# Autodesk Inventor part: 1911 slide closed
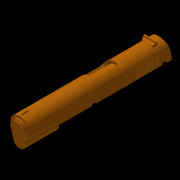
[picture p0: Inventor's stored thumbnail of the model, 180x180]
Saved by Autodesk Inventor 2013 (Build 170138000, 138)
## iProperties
Created: 2012-12
Part Number: 1911 slide closed
Material: Generic
Document SubType Name: Modeling
Designer: John
Density: 1 g/cm^3
Author: John
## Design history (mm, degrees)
sketch "Sketch1"
  geometry: L1 (-11.633, -12.598)-(-11.633, 4.424); L2 (11.633, -12.598)-(11.633, 4.424); L3 (-8.128, -16.129)-(-8.128, -12.598); L4 (8.128, -16.129)-(8.128, -12.598); L5 (-11.633, -12.598)-(-8.128, -12.598); L6 (8.128, -12.598)-(11.633, -12.598); C1 r 8.877 at (0, 0); C2 r 6.35 at (0, -16.129); A1 r 12.446 centre (0, 0) between (11.633, 4.424) and (-11.633, 4.424); A2 r 8.128 centre (0, -16.129) between (-8.128, -16.129) and (8.128, -16.129); 1 further point
  constraints: 12 end point, 4 centre point, 4 perpendicular, 4 point on circle, 3 coincident, 2 tangent
  dimensions: "d9" = 12.7 diameter of C2
extrude "Extrusion1" new body sketch "Sketch1" distance "d10" = 43.1292; taper "d11" = 0 deg
sketch "Sketch2"
  geometry: L1 (11.633, -12.598)-(11.633, 4.424) reference; L2 (-11.633, 4.424)-(-11.633, -12.598) reference; L3 (-8.877, 0)-(-8.877, -12.598); L4 (8.877, 0)-(8.877, -12.598); L5 (-11.633, -12.598)-(-8.877, -12.598); L6 (8.877, -12.598)-(11.633, -12.598); A1 r 8.877 centre (0, 0) between (-8.877, 0) and (8.877, 0) reference; A2 r 12.446 centre (0, 0) between (11.633, 4.424) and (-11.633, 4.424) reference
  constraints: 8 end point, 6 perpendicular, 2 point on circle, 2 tangent
extrude "Extrusion2" join sketch "Sketch2" distance "d12" = 138.6332; taper "d13" = 0 deg
sketch "Sketch3"
  geometry: L1 (181.762, 17.022)-(181.762, 0) reference; L2 (181.762, 17.022)-(181.762, 25.044) reference; L3 (181.762, 0)-(189.144, 0); A1 r 46.177 centre (142.967, 0) between (189.144, 0) and (181.762, 25.044); 1 further point
  constraints: 2 end point, 2 point on circle, 1 centre point, 1 perpendicular
extrude "Extrusion3" join sketch "Sketch3" stored distance "d15" = 24.892; taper "d16" = 0 deg
sketch "Sketch4"
  geometry: L1 (-11.633, -12.598)-(-11.633, 4.424) reference; L2 (11.633, 4.424)-(11.633, -12.598) reference; L3 (-11.633, 1.975)-(-14.32, 1.975); L4 (-14.32, 1.975)-(-14.32, 15.401); L5 (-14.32, 15.401)-(14.052, 15.401); L6 (14.052, 15.401)-(14.052, 2.651); L7 (14.052, 2.651)-(11.633, 2.651); A1 r 12.446 centre (0, 0) between (11.633, 4.424) and (-11.633, 4.424) reference
  constraints: 10 end point, 3 perpendicular, 2 parallel, 2 point on line
extrude "Extrusion4" cut sketch "Sketch4" stored distance "d17" = 24.892; taper "d18" = 0 deg
sketch "Sketch5"
  geometry: L1 (-19.761, 43.129)-(-19.761, -146.015) reference; L2 (3.505, -146.015)-(-19.761, -146.015) reference; L3 (3.505, 43.129)-(3.505, -146.015) reference; L4 (-16.256, 43.129)-(-16.256, 0) reference; L5 (3.505, -144.665)-(3.505, -148.55); L6 (3.505, -148.55)-(-19.761, -148.55); L7 (-19.761, -148.55)-(-19.761, -144.665); A1 r 50.8 centre (-8.128, -95.215) between (-19.761, -144.665) and (3.505, -144.665); A2 r 50.8 centre (-8.128, -95.215) between (3.505, -45.765) and (-19.761, -45.765); 1 further point
  constraints: 6 end point, 4 point on circle, 4 point on line, 2 centre point, 2 parallel, 1 perpendicular
sketch "Sketch6"
  geometry: A1 r 46.177 centre (-12.598, -142.967) between (-12.598, -189.144) and (12.446, -181.762); 1 further point
  constraints: 2 point on circle, 1 centre point
sketch "Sketch8"
  geometry: L1 (3.505, 43.129)-(0, 43.129) reference; L2 (5.944, 43.129)-(0, 43.129); L3 (5.944, 43.129)-(5.944, 1.079); L4 (5.944, 1.079)-(0, 1.079); L5 (0, 20.366)-(0, 43.129); A1 r 34.267 centre (34.267, 20.366) between (0, 20.366) and (5.944, 1.079); 1 further point
  constraints: 8 end point, 2 perpendicular, 2 point on circle, 1 centre point, 1 collinear, 1 tangent
revolve "Revolution1" sketch "Sketch8" stored, may be unused: angle "d23" = 90 deg
mirror "Mirror1"
sketch "Sketch9"
  geometry: L1 (-9.576, -9.601)-(9.576, -9.601); L2 (-11.633, 4.424)-(-11.633, -7.178) reference; L3 (-8.128, -12.598)-(-11.633, -12.598) reference; L4 (11.633, -7.178)-(11.633, 4.424) reference; L5 (11.633, -12.598)-(8.128, -12.598) reference; L6 (-11.633, -7.178)-(-11.633, -12.598); L7 (11.633, -12.598)-(11.633, -7.178); L8 (-9.576, -7.036)-(9.576, -7.036); L9 (-9.576, -9.601)-(-9.576, -7.036); L10 (9.576, -9.601)-(9.576, -7.036); A1 r 12.446 centre (0, 0) between (11.633, 4.424) and (-11.633, 4.424) reference; 1 further point
  constraints: 12 end point, 3 perpendicular, 1 parallel
extrude "Extrusion5" cut sketch "Sketch9" stored distance "d31" = 25.4; taper "d32" = 0 deg
sketch "Sketch10"
  geometry: L1 (12.446, 0)-(12.446, -181.762) reference; L2 (-12.598, -37.861)-(-12.598, -189.144) reference; L3 (12.446, -181.762)-(-12.598, -181.762); L4 (-12.598, -181.762)-(13.56, -181.762); L5 (13.56, -181.762)-(13.56, -201.516); L6 (13.56, -201.516)-(-12.598, -201.516); L7 (-12.598, -201.516)-(-12.598, -181.762); 2 further points
  constraints: 10 end point, 2 parallel, 2 perpendicular, 1 horizontal, 1 point on line
extrude "Extrusion6" cut sketch "Sketch10" stored distance "d33" = 8.001; taper "d34" = 0 deg
sketch "Sketch11"
  geometry: L1 (4.877, -2.565)-(4.877, -5.563) reference; L2 (-2.756, -5.563)-(4.877, -5.563) reference; L3 (-2.756, 11.46)-(-2.756, -5.563) reference; L4 (4.877, 18.821)-(4.877, 0) reference; L5 (4.877, 0)-(-0.698, 0) reference; L6 (-0.698, 0)-(-0.698, -2.565) reference; L7 (-0.698, -2.565)-(4.877, -2.565) reference; L8 (12.878, -5.563)-(12.878, -2.565) reference; L9 (12.878, -2.565)-(18.453, -2.565) reference; L10 (18.453, -2.565)-(18.453, 0) reference; L11 (18.453, 0)-(12.878, 0) reference; L12 (12.878, 0)-(12.878, 18.821) reference; L13 (20.511, -5.563)-(20.511, 11.46) reference; L14 (12.878, -5.563)-(20.511, -5.563) reference; L15 (17.755, 0)-(17.755, 7.036) reference; L16 (17.755, -5.563)-(17.755, -2.565) reference; L17 (0, -2.565)-(0, -5.563) reference; A1 r 8.877 centre (8.877, 7.036) between (17.755, 7.036) and (12.878, 14.961) reference
  constraints: 2 other
extrude "Extrusion7" cut sketch "Sketch11" stored distance "d35" = 8.001; taper "d36" = 0 deg
sketch "Sketch12"
  geometry: L1 (8.877, -12.598)-(8.877, -9.601) reference; L2 (7.988, -12.598)-(7.988, -9.601); L3 (7.988, -9.601)-(8.877, -9.601); L4 (7.988, -12.598)-(8.877, -12.598); L5 (0, -12.394)-(0, -11.1); L6 (-7.988, -12.598)-(-8.877, -12.598); L7 (-8.128, -12.598)-(-8.877, -12.598); L8 (-8.877, -12.598)-(-8.877, -9.601); L9 (-7.988, -12.598)-(-7.988, -9.601); L10 (-7.988, -9.601)-(-8.877, -9.601); L11 (-8.877, -9.601)-(-9.576, -9.601)
  constraints: 20 end point, 2 perpendicular, 2 symmetric about line
extrude "Extrusion8" join sketch "Sketch12" distance "d38" = 146.812; taper "d39" = 0 deg
sweep "Sweep2" dims "d40" = 0
workplane "Work Plane1"
sketch "Sketch13"
  geometry: L1 (5.537, -124.206)-(-5.537, -124.206); L2 (-5.537, -124.206)-(-5.537, -95.148); L3 (-1.575, -91.186)-(5.537, -91.186); L4 (5.537, -91.186)-(5.537, -124.206); A1 r 3.962 centre (-1.575, -95.148) between (-1.575, -91.186) and (-5.537, -95.148); 1 further point
  constraints: 8 end point, 2 point on circle, 2 tangent, 1 centre point, 1 parallel, 1 perpendicular
  dimensions: "d45" = 3.9624 radius of A1
sketch "Sketch14"
  geometry: L1 (4.648, -16.129)-(4.648, -7.563); L2 (4.648, -16.129)-(-4.648, -16.129); L3 (-4.648, -16.129)-(-4.648, -7.563); C1 r 6.35 at (0, -16.129) reference; A1 r 8.877 centre (0, 0) between (4.648, -7.563) and (-4.648, -7.563) reference
  constraints: 6 end point, 2 perpendicular, 2 point on circle
  dimensions: "d46" = 4.6482 distance of C1.centre L1.start; "d47" = 9.2964 distance of L1.start L2.end
extrude "Extrusion9" cut sketch "Sketch14" distance "d48" = 146.812; taper "d49" = 0 deg
extrude "Extrusion10" cut sketch "Sketch13" distance "d50" = 9.525; taper "d51" = 0 deg
workplane "Work Plane3"
sketch "Sketch15"
  geometry: L1 (91.186, -9.064)-(124.206, -9.064) reference; L2 (91.186, -9.064)-(120.142, -9.064); L3 (0, 0)-(184.436, 0) reference; L4 (120.142, -9.064)-(120.142, -3.962); L5 (91.186, -9.064)-(91.186, -3.962); L6 (95.148, 0)-(116.18, 0); L7 (124.206, -9.064)-(120.142, -9.064); A1 r 3.962 centre (116.18, -3.962) between (120.142, -3.962) and (116.18, 0); A2 r 3.962 centre (95.148, -3.962) between (95.148, 0) and (91.186, -3.962); 3 further points
  constraints: 10 end point, 7 point on line, 4 point on circle, 4 tangent, 2 centre point, 2 collinear, 1 equal radius, 1 parallel, 1 perpendicular
  dimensions: "d55" = 3.9624 radius of A1
extrude "Extrusion11" cut sketch "Sketch15" distance "d56" = 9.525; taper "d57" = 0 deg
fillet "Fillet1" dims "d58" = 3.175
sketch "Sketch16"
  geometry: L1 (-16.256, 0)-(0, 0) reference; L2 (3.505, -97.384)-(2.921, -98.83); L3 (2.921, -98.83)-(3.505, -99.048); L4 (3.505, -97.384)-(3.505, -99.048); 1 further point
  constraints: 6 end point
extrude "Extrusion12" cut sketch "Sketch16" stored distance "d65" = 25.4; taper "d66" = 0 deg
mirror "Mirror2"
sketch "Sketch17"
  geometry: L1 (4.424, 0)-(12.446, 0) reference; L2 (10.906, -1.575)-(13.297, -1.575); L3 (10.906, -6.858)-(10.906, -1.575); L4 (10.906, -6.858)-(10.906, -12.141); L5 (10.906, -12.141)-(13.32, -12.141); L6 (13.454, -11.731)-(13.323, -11.474); L7 (13.579, -11.344)-(13.323, -11.474); L8 (13.454, -11.731)-(13.32, -12.141); L9 (13.705, -10.958)-(13.449, -11.088); L10 (13.579, -11.344)-(13.449, -11.088); L11 (13.83, -10.571)-(13.574, -10.701); L12 (13.705, -10.958)-(13.574, -10.701); L13 (13.956, -10.184)-(13.7, -10.315); L14 (13.83, -10.571)-(13.7, -10.315); L15 (14.082, -9.798)-(13.825, -9.928); L16 (13.956, -10.184)-(13.825, -9.928); L17 (14.207, -9.411)-(13.951, -9.542); L18 (14.082, -9.798)-(13.951, -9.542); L19 (14.333, -9.025)-(14.077, -9.155); L20 (14.207, -9.411)-(14.077, -9.155); L21 (14.458, -8.638)-(14.202, -8.769); L22 (14.333, -9.025)-(14.202, -8.769); L23 (14.584, -8.252)-(14.328, -8.382); L24 (14.458, -8.638)-(14.328, -8.382); L25 (14.709, -7.865)-(14.453, -7.996); L26 (14.584, -8.252)-(14.453, -7.996); L27 (14.835, -7.479)-(14.579, -7.609); L28 (14.709, -7.865)-(14.579, -7.609); L29 (14.961, -7.092)-(14.705, -7.223); L30 (14.835, -7.479)-(14.705, -7.223); L31 (15.037, -6.858)-(14.961, -7.092); A1 r 8.89 centre (6.147, -6.858) between (15.037, -6.858) and (13.297, -1.575); 1 further point
  constraints: 60 end point, 14 perpendicular, 2 point on circle, 1 centre point, 1 collinear, 1 point on line
extrude "Extrusion13" join sketch "Sketch17" stored distance "d79" = 2.032; taper "d80" = 0 deg
sketch "Sketch18"
  geometry: L1 (37.861, -5.42)-(140.513, -5.42) reference; L2 (124.206, 19.398)-(124.206, 19.624) reference; L3 (88.613, -3.507)-(88.787, -4.743) reference; L4 (84.901, -3.033)-(87.778, -2.832) reference; L5 (81.143, -5.42)-(89.566, -5.42); A1 r 0.787 centre (87.833, -3.617) between (88.613, -3.507) and (87.778, -2.832) reference; A2 r 1.981 centre (85.039, -5.009) between (84.901, -3.033) and (83.272, -4.113) reference; A3 r 2.388 centre (81.143, -3.033) between (81.143, -5.42) and (83.272, -4.113); A4 r 0.787 centre (89.566, -4.633) between (88.787, -4.743) and (89.566, -5.42); 2 further points
  constraints: 8 point on circle, 7 tangent, 6 end point, 4 centre point, 3 point on line, 4 other
extrude "Extrusion14" cut sketch "Sketch18" distance "d90" = 2.413; taper "d91" = 0 deg
sketch "Sketch19"
  geometry: L1 (12.22, -124.206)-(12.446, -124.206) reference; L2 (-12.598, -43.129)-(-12.598, -188.512) reference; L3 (8.433, -175.773)-(8.433, -165.781); L4 (8.433, -173.276)-(8.433, -175.773); L5 (12.446, 0)-(12.446, -181.762) reference; L6 (9.525, -166.376)-(12.449, -167.74) reference; L7 (9.525, -175.177)-(12.449, -173.814) reference; L8 (9.525, -166.376)-(9.525, -175.177) reference; L9 (9.525, -171.539)-(9.525, -170.015); L10 (15.748, -171.539)-(15.479, -170.015) reference; L11 (14.834, -170.015)-(15.479, -170.015); L12 (15.748, -171.539)-(14.834, -171.539); A1 r 2.388 centre (14.834, -167.627) between (12.449, -167.74) and (14.834, -170.015); A2 r 2.388 centre (14.834, -173.927) between (14.834, -171.539) and (12.449, -173.814); 2 further points
  constraints: 18 end point, 4 point on circle, 2 centre point, 2 perpendicular, 2 point on line, 2 tangent, 1 horizontal, 1 midpoint, 1 vertical, 4 other
extrude "Extrusion15" join sketch "Sketch19" stored distance "d111" = 15.9004; taper "d112" = 0 deg
workplane "Work Plane4"
sketch "Sketch20"
  geometry: L1 (7.95, -166.4)-(7.95, -175.154) reference; L2 (-7.95, -175.154)-(-7.95, -166.4) reference; L3 (1.016, -1.575)-(1.016, -12.141) reference; L4 (1.016, -12.141)-(-1.016, -12.141) reference; L5 (-1.016, -12.141)-(-1.016, -1.575) reference; L6 (-1.016, -1.575)-(1.016, -1.575) reference; L7 (11.633, -172.136)-(11.049, -171.917) reference; L8 (11.049, -171.917)-(11.633, -170.471) reference; L9 (11.633, -170.471)-(11.049, -170.253) reference; L10 (11.049, -170.253)-(11.633, -168.807) reference; L11 (11.633, -168.807)-(11.049, -168.589) reference; L12 (11.049, -168.589)-(11.633, -167.143) reference; L13 (11.633, -167.143)-(11.049, -166.924) reference; L14 (11.049, -166.924)-(11.633, -165.478) reference; L15 (11.633, -165.478)-(11.049, -165.26) reference; L16 (11.049, -165.26)-(11.633, -163.814) reference; L17 (11.633, -163.814)-(11.049, -163.596) reference; L18 (11.049, -163.596)-(11.633, -162.15) reference; L19 (11.633, -162.15)-(11.049, -161.931) reference; L20 (11.049, -161.931)-(11.633, -160.485) reference; L21 (11.633, -160.485)-(11.049, -160.267) reference; L22 (11.049, -160.267)-(11.633, -158.821) reference; L23 (11.633, -158.821)-(11.049, -158.602) reference; L24 (11.049, -158.602)-(11.633, -157.156) reference; L25 (11.633, -157.156)-(11.049, -156.938) reference; L26 (11.049, -156.938)-(11.633, -155.492) reference; L27 (11.633, -155.492)-(11.049, -155.274) reference; L28 (11.049, -155.274)-(11.633, -153.828) reference; L29 (11.633, -153.828)-(11.049, -153.609) reference; L30 (11.049, -153.609)-(11.633, -152.163) reference; L31 (11.633, -152.163)-(11.049, -151.945) reference; L32 (11.049, -151.945)-(11.633, -150.499) reference; L33 (11.633, -150.499)-(11.049, -150.281) reference; L34 (11.049, -150.281)-(11.633, -148.835) reference; L35 (11.633, -148.835)-(11.049, -148.616) reference; L36 (11.049, -148.616)-(11.633, -147.17) reference; L37 (11.633, -147.17)-(11.049, -146.952) reference; L38 (11.049, -146.952)-(11.633, -145.506) reference; L39 (11.633, -145.506)-(11.049, -145.287) reference; L40 (11.049, -145.287)-(11.633, -143.842) reference; L41 (11.633, -143.842)-(11.049, -143.623) reference; L42 (11.049, -143.623)-(11.633, -142.177) reference; L43 (11.633, -142.177)-(11.049, -141.959) reference; L44 (11.049, -141.959)-(11.633, -140.513) reference; L45 (11.633, -116.18)-(11.633, -140.513) reference; L46 (9.567, -120.142)-(5.537, -120.142) reference; L47 (5.537, -120.142)-(5.537, -121.031) reference; L48 (2.362, -124.206)-(-2.362, -124.206) reference; L49 (-5.537, -121.031)-(-5.537, -95.148) reference; L50 (-1.575, -91.186)-(9.567, -91.186) reference; L51 (11.633, 0)-(11.633, -95.148) reference; L52 (11.633, 0)-(-11.633, 0) reference; L53 (-11.633, 0)-(-11.633, -140.513) reference; L54 (-11.633, -140.513)-(-11.049, -141.959) reference; L55 (-11.049, -141.959)-(-11.633, -142.177) reference; L56 (-11.633, -142.177)-(-11.049, -143.623) reference; L57 (-11.049, -143.623)-(-11.633, -143.842) reference; L58 (-11.633, -143.842)-(-11.049, -145.287) reference; L59 (-11.049, -145.287)-(-11.633, -145.506) reference; L60 (-11.633, -145.506)-(-11.049, -146.952) reference; L61 (-11.049, -146.952)-(-11.633, -147.17) reference; L62 (-11.633, -147.17)-(-11.049, -148.616) reference; L63 (-11.049, -148.616)-(-11.633, -148.835) reference; L64 (-11.633, -148.835)-(-11.049, -150.281) reference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; A1 r 7.874 centre (0, -170.777) between (6.794, -174.756) and (6.794, -166.797); A2 r 7.874 centre (0, -170.777) between (-6.794, -166.797) and (-6.794, -174.756); 3 further points; 2 other entities
  constraints: 4 point on circle, 2 centre point, 13 other
extrude "Extrusion16" cut sketch "Sketch20" stored distance "d115" = 15.9004; taper "d116" = 0 deg
sketch "Sketch21" dims "d57" = 0
  geometry: L1 (15.674, 0)-(0, 0) reference; L2 (15.674, -0.914)-(0, -0.914) reference; L3 (7.837, 0)-(8.853, 0); L4 (8.853, 0)-(8.853, -1.016); L5 (8.853, -1.016)-(6.821, -1.016); L6 (6.821, -1.016)-(6.821, 0); 1 further point
  constraints: 8 end point, 2 perpendicular, 2 point on line, 1 midpoint, 1 parallel
  dimensions: "d117" = 1.016 distance of L3.start L3.end; "d118" = 1.016 distance of L3.end L4.end; "d119" = 2.032 distance of L4.end L5.end
extrude "Extrusion17" cut sketch "Sketch21" distance "d120" = 15.9004; taper "d121" = 0 deg
sketch "Sketch22"
  geometry: L1 (-37.861, -5.42)-(-140.513, -5.42) reference; L2 (-116.18, 11.602)-(-140.513, 11.602) reference; L3 (-47.574, -5.42)-(-47.574, -5.166); L4 (-47.574, -5.166)-(-11.382, -5.166); L5 (-11.382, -5.166)-(-11.382, -6.538); L6 (-11.382, -6.538)-(-47.574, -6.538); L7 (-47.574, -6.538)-(-47.574, -5.42); 1 further point
  constraints: 10 end point, 3 perpendicular, 2 parallel, 1 point on line
  dimensions: "d122" = 0.254 distance of L3.start L3.end
extrude "Extrusion18" cut sketch "Sketch22" stored distance "d124" = 25.4; taper "d125" = 0 deg
sketch "Sketch23"
  geometry: L1 (-47.574, -5.166)-(-37.834, -5.166) reference; L2 (-43.129, -8.951)-(-43.129, -5.42) reference; L3 (-43.129, -5.42)-(-43.129, -5.166); L4 (-43.129, -5.166)-(-189.167, -5.166); L5 (-189.167, -5.166)-(-189.167, -5.785); L6 (-189.167, -5.785)-(-43.129, -5.785); L7 (-43.129, -5.785)-(-43.129, -5.42); 1 further point
  constraints: 10 end point, 5 perpendicular, 2 point on line
mirror "Mirror3"
extrude "Extrusion19" cut sketch "Sketch23" distance "d126" = 25.4; taper "d127" = 0 deg
sketch "Sketch24"
  geometry: L1 (13.857, 14.915)-(67.695, 14.915); L2 (9.2, -2.465)-(6.411, -12.874); L3 (-9.2, -2.465)-(-6.411, -12.874); C1 r 7.379 at (0, 0); A1 r 9.525 centre (0, 0) between (9.2, -2.465) and (-9.2, -2.465) reference; A2 r 5.004 centre (0, -16.078) between (4.135, -13.261) and (-4.135, -13.261) reference; A3 r 1.27 centre (5.185, -12.545) between (4.135, -13.261) and (6.411, -12.874); A4 r 1.27 centre (-5.185, -12.545) between (-6.411, -12.874) and (-4.135, -13.261)
  constraints: 8 point on circle, 6 end point, 5 centre point, 3 tangent, 1 coincident, 1 horizontal, 2 other
  dimensions: "d140" = 14.7574 diameter of C1
extrude "Extrusion20" join sketch "Sketch24" distance "d141" = 2.3114; taper "d142" = 0 deg
sketch "Sketch25"
  geometry: L1 (-4.648, -7.563)-(-4.648, -11.803) reference; L2 (-4.648, -7.563)-(-4.648, -5.731); L3 (4.648, -7.563)-(4.648, -5.731); A1 r 8.877 centre (0, 0) between (4.648, -7.563) and (-4.648, -7.563) reference; A2 r 7.379 centre (0, 0) between (-4.648, -5.731) and (4.648, -5.731) reference
  constraints: 4 end point, 2 point on circle, 1 collinear, 1 parallel
extrude "Extrusion21" join sketch "Sketch25" stored distance "d143" = 2.3114; taper "d144" = 0 deg
sketch "Sketch27"
  geometry: C1 r 5.004 at (0, -16.078); A1 r 5.004 centre (0, -16.078) between (4.135, -13.261) and (-4.135, -13.261) reference
  constraints: 1 centre point, 1 coincident
extrude "Extrusion23" join sketch "Sketch27" distance "d147" = 1.524; taper "d148" = 0 deg
sketch "Sketch28"
  geometry: C1 r 6.35 at (0, -16.129); A1 r 6.35 centre (0, -16.129) between (-5.839, -13.634) and (5.839, -13.634) reference; A2 r 8.128 centre (0, -16.129) between (-8.128, -16.129) and (8.128, -16.129) reference; A3 r 5.004 centre (0, -16.078) between (-4.135, -13.261) and (4.135, -13.261) reference; A4 r 5.004 centre (0, -16.078) between (4.135, -13.261) and (-4.135, -13.261) reference
  constraints: 1 centre point, 1 coincident, 1 concentric
extrude "Extrusion24" join sketch "Sketch28" stored distance "d149" = 41.3385; taper "d150" = 0 deg
sketch "Sketch31"
  geometry: L1 (-4.877, 0)-(0, 0) reference; L2 (0, 0)-(0, 7.036) reference; L3 (-12.878, 0)-(-12.878, 14.961) reference; L4 (-17.755, 7.036)-(-17.755, 0) reference; L5 (-17.755, 0)-(-12.878, 0) reference; L6 (-12.878, 0)-(-4.877, 0); A1 r 8.877 centre (-8.877, 7.036) between (0, 7.036) and (-4.877, 14.961) reference; A2 r 8.877 centre (-8.877, 7.036) between (-12.878, 14.961) and (-17.755, 7.036) reference; A3 r 8.877 centre (-8.877, 7.036) between (0, 7.036) and (-17.755, 7.036)
  constraints: 2 end point, 2 point on circle, 2 point on line, 1 centre point, 1 coincident, 1 collinear, 1 concentric
extrude "Extrusion27" join sketch "Sketch31" stored distance "d158" = 55.5625; taper "d159" = 0 deg
workplane "Work Plane5"
sketch "Sketch32"
  geometry: L1 (18.453, -2.565)-(16.866, -2.565) reference; A1 r 8.877 centre (8.877, 7.036) between (17.755, 7.036) and (0, 7.036) reference; A2 r 8.877 centre (8.877, 8.369) between (17.73, 7.703) and (0.025, 7.703); 2 further points
  constraints: 4 point on circle, 1 centre point, 1 coincident
extrude "Extrusion28" cut sketch "Sketch32" distance "d163" = 4.5212; taper "d164" = 0 deg
workplane "Work Plane6"
sketch "Sketch33"
  geometry: L1 (-2.451, -16.54)-(-4.039, -16.54) reference; A1 r 8.877 centre (5.537, -5.605) between (14.389, -6.272) and (-3.315, -6.272); A2 r 8.877 centre (5.537, -6.939) between (14.389, -6.272) and (-3.315, -6.272) reference; 1 further point
  constraints: 4 point on circle, 1 centre point
extrude "Extrusion29" cut sketch "Sketch33" distance "d168" = 4.5212; taper "d169" = 0 deg
sketch "Sketch34"
  geometry: L1 (37.834, -5.166)-(47.574, -5.166) reference; L2 (47.574, -5.166)-(82.215, -5.166) reference; L3 (176.354, -2.313)-(174.501, -5.166); L4 (178.111, -1.94)-(183.079, -5.166) reference; L5 (174.501, -5.166)-(183.079, -5.166); A1 r 1.27 centre (177.419, -3.005) between (178.111, -1.94) and (176.354, -2.313) reference; 1 further point
  constraints: 6 end point, 2 point on circle, 2 point on line, 2 tangent, 1 centre point, 1 collinear, 1 perpendicular, 3 other
extrude "Extrusion30" cut sketch "Sketch34" distance "d183" = 7.6962; taper "d184" = 0 deg
sketch "Sketch35"
  geometry: A1 r 5.004 centre (0, -16.078) between (4.135, -13.261) and (-4.135, -13.261) reference; A2 r 5.004 centre (0, -16.078) between (-4.135, -13.261) and (4.135, -13.261) reference; 1 further point
extrude "Extrusion31" join sketch "Sketch35" distance "d185" = 3.175; taper "d186" = 0 deg
workplane "Work Plane7"
sketch "Sketch36"
  geometry: L1 (4.648, -11.803)-(4.648, -5.731) reference; L2 (-4.648, -5.731)-(-4.648, -11.803) reference; L3 (0, -16.078)-(5.004, -16.078); L4 (5.004, -16.078)-(5.004, -5.423); L5 (0, -16.078)-(-5.004, -16.078); L6 (-5.004, -16.078)-(-5.004, -5.423); A1 r 6.35 centre (0, -16.129) between (4.648, -11.803) and (-4.648, -11.803) reference; A2 r 7.379 centre (0, 0) between (4.648, -5.731) and (-4.648, -5.731) reference; A3 r 5.004 centre (0, -16.078) between (5.004, -16.078) and (-5.004, -16.078) reference; 1 further point
  constraints: 8 end point, 4 point on circle, 3 perpendicular, 2 tangent, 1 parallel
extrude "Extrusion32" cut sketch "Sketch36" stored distance "d188" = 12.7; taper "d189" = 0 deg
sketch "Sketch37"
  geometry: L1 (0, 0)-(6.35, 0); L2 (6.35, 0)-(6.35, -9.525); L3 (6.35, -9.525)-(-6.35, -9.525); L4 (-6.35, -9.525)-(-6.35, 0); L5 (-6.35, 0)-(0, 0); 1 further point
  constraints: 10 end point, 2 parallel, 2 perpendicular
  dimensions: "d190" = 6.35 distance of L1.start L1.end; "d192" = 12.7 distance of L2.end L3.end
extrude "Extrusion33" cut sketch "Sketch37" distance "d193" = 25.4; taper "d194" = 0 deg
sketch "Sketch38"
  geometry: C1 r 7.379 at (0, 0) reference; C2 r 7.874 at (0, 0); A1 r 9.525 centre (0, 0) between (9.2, -2.465) and (-9.2, -2.465) reference
  constraints: 1 centre point, 1 coincident
  dimensions: "d195" = 15.748 diameter of C2
extrude "Extrusion34" cut sketch "Sketch38" distance "d197" = 55.5625; taper "d198" = 0 deg
sketch "Sketch39"
  geometry: L1 (0, 0)-(17.755, 0) reference; L2 (11.239, 19.256)-(11.239, 15.593) reference; L3 (0, 0)-(0, -7.053); L4 (0, -7.053)-(17.755, -7.053); L5 (17.755, -7.053)-(17.755, 0)
  constraints: 6 end point, 2 parallel, 1 perpendicular
extrude "Extrusion35" cut sketch "Sketch39" distance "d199" = 76.2; taper "d200" = 0 deg
sketch "Sketch40"
  geometry: L1 (-11.633, -12.344)-(-11.633, -12.09); L2 (-11.633, -12.09)-(11.633, -12.09); L3 (11.633, -12.09)-(11.633, -12.344); L4 (11.633, -12.344)-(-11.633, -12.344); 3 further points
  constraints: 8 end point, 2 horizontal alignment, 2 perpendicular, 1 parallel, 1 vertical
  dimensions: "d201" = 0.254 distance of L1.start L1.end
extrude "Extrusion36" cut sketch "Sketch40" stored distance "d202" = 25.4; taper "d203" = 0 deg
sketch "Sketch41"
  geometry: L1 (11.633, -12.09)-(7.988, -12.09) reference; L2 (8.128, -12.344)-(11.633, -12.344) reference; L3 (8.128, -12.344)-(8.128, -12.09); L4 (11.633, -12.09)-(11.633, -12.344); L5 (0, -9.357)-(0, -11.651); L6 (-11.633, -12.09)-(-11.633, -12.344); L7 (-8.128, -12.344)-(-8.128, -12.09); L8 (-11.633, -12.09)-(-8.128, -12.09); L9 (-8.128, -12.344)-(-11.633, -12.344); 2 further points
  constraints: 14 end point, 5 symmetric about line, 2 parallel, 1 perpendicular, 1 point on line
extrude "Extrusion37" cut sketch "Sketch41" distance "d204" = 85.725; taper "d205" = 0 deg
sketch "Sketch43"
  geometry: C1 r 7.874 at (0, 0) reference
extrude "Extrusion39" join sketch "Sketch43" distance "d208" = 46.0375; taper "d210" = 0 deg; dims "d209" = 1.5875, "d211" = 0
sketch "Sketch44"
  geometry: L1 (0, 0)-(0, 7.036) reference; L2 (0, 0)-(17.755, 0) reference; L3 (17.755, 7.036)-(17.755, 0) reference; L4 (1.257, 7.036)-(1.257, 0); L5 (16.497, 7.036)-(16.497, 0); A1 r 8.877 centre (8.877, 7.036) between (17.755, 7.036) and (11.239, 15.593) reference; A2 r 12.446 centre (8.877, 7.036) between (11.239, 19.256) and (6.515, 19.256) reference; A3 r 7.62 centre (8.877, 7.036) between (16.497, 7.036) and (1.257, 7.036); A4 r 8.877 centre (8.877, 7.036) between (17.755, 7.036) and (0, 7.036)
  constraints: 5 point on circle, 4 end point, 4 point on line, 2 centre point, 2 coincident, 2 perpendicular, 2 tangent
  dimensions: "d212" = 15.24 diameter of A3
extrude "Extrusion40" join sketch "Sketch44" distance "d213" = 119.0625; taper "d214" = 0 deg
sketch "Sketch45"
  geometry: L1 (-8.128, -12.09)-(-8.128, -12.344) reference; L2 (-8.128, -12.344)-(-8.128, -16.129); L3 (-8.128, -12.09)-(-8.128, -0.992); L4 (8.128, -12.344)-(8.128, -12.09) reference; L5 (8.128, -12.09)-(8.128, -0.992); L6 (8.128, -0.992)-(-8.128, -0.992); L7 (8.128, -12.344)-(8.128, -16.129); A1 r 8.128 centre (0, -16.129) between (-8.128, -16.129) and (8.128, -16.129) reference
  constraints: 10 end point, 3 collinear, 2 perpendicular, 2 point on circle
extrude "Extrusion41" join sketch "Sketch45" distance "d215" = 42.8625; taper "d216" = 0 deg
body "Solid1"
pattern_linear "Rectangular Pattern1" dims "d69" = 1.66437
node "Projected Loop3"
node "Projected Loop4"
node "Projected Loop6"
other parameters: "d113" = 4.7625, "d133" = 105 deg, "d138" = 105 deg, "d160" = 37.1348, "d165" = 41.4274, "d187" = -43.1292
